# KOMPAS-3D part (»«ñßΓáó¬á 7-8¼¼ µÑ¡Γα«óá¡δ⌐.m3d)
File: created 10.02.2016 13:21:24, last saved 22.07.2016 14:57:17.
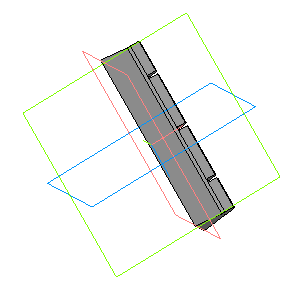
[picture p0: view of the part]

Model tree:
1. Эскиз:1
2. Операция выдавливания:1
     Расстояние 1 = 25.3; Расстояние 2 = 25.3
3. Эскиз:2
4. Вырезать элемент выдавливания:1
     Расстояние 1 = 2.5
